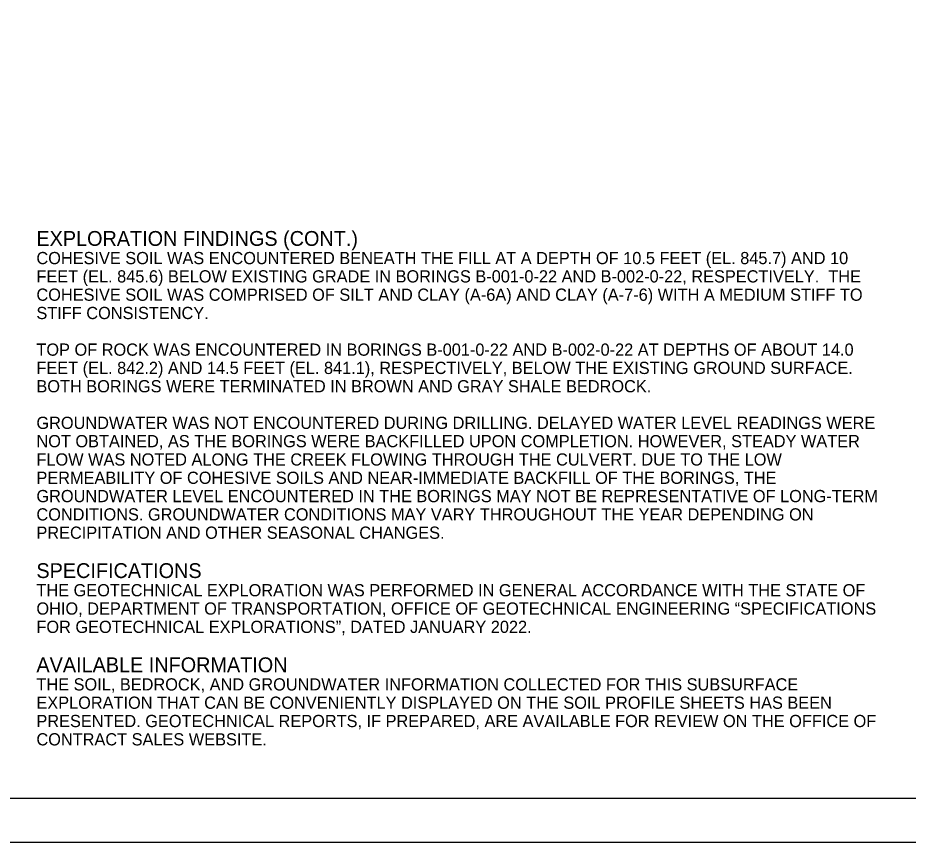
# Model space of a CAD drawing. Extents: x 0 to 34, y 0 to 22.
# Drawn here: x 11.81 to 22.03, y 0 to 9.46 of the extents above; entities that cross this region are included whole.
import ezdxf

# ---------------------------------------------------------------- set-up
doc = ezdxf.new("R2010")
doc.units = 0
for name, color, linetype in [('SH_Border', 7, 'Continuous'), ('SH_Cut_Line', 7, 'Continuous'), ('SH_Text', 7, 'Continuous')]:
    doc.layers.add(name, color=color, linetype=linetype)

msp = doc.modelspace()

# ---------------------------------------------------------------- linework, layer by layer
at = {"layer": 'SH_Border'}
msp.add_lwpolyline([(1.5, 21.5), (33.5, 21.5), (33.5, 0.5), (1.5, 0.5)], close=True, dxfattribs=at)
at = {"layer": 'SH_Cut_Line'}
msp.add_lwpolyline([(0, 0), (34, 0), (34, 22), (0, 22)], close=True, dxfattribs=at)

# ---------------------------------------------------------------- texts
at = {"layer": 'SH_Text'}
for s, height, p in [('EXPLORATION FINDINGS (CONT.)', 0.17, (12.028, 6.84)), ('COHESIVE SOIL WAS ENCOUNTERED BENEATH THE FILL AT A DEPTH OF 10.5 FEET (EL. 845.7) AND 10 ', 0.14, (12.028, 6.63)), ('FEET (EL. 845.6) BELOW EXISTING GRADE IN BORINGS B-001-0-22 AND B-002-0-22, RESPECTIVELY.  THE ', 0.14, (12.028, 6.42)), ('COHESIVE SOIL WAS COMPRISED OF SILT AND CLAY (A-6A) AND CLAY (A-7-6) WITH A MEDIUM STIFF TO ', 0.14, (12.028, 6.21)), ('STIFF CONSISTENCY.', 0.14, (12.028, 6)), ('TOP OF ROCK WAS ENCOUNTERED IN BORINGS B-001-0-22 AND B-002-0-22 AT DEPTHS OF ABOUT 14.0 ', 0.14, (12.028, 5.58)), ('FEET (EL. 842.2) AND 14.5 FEET (EL. 841.1), RESPECTIVELY, BELOW THE EXISTING GROUND SURFACE. ', 0.14, (12.028, 5.37)), ('BOTH BORINGS WERE TERMINATED IN BROWN AND GRAY SHALE BEDROCK. ', 0.14, (12.028, 5.16)), ('GROUNDWATER WAS NOT ENCOUNTERED DURING DRILLING. DELAYED WATER LEVEL READINGS WERE ', 0.14, (12.028, 4.74)), ('NOT OBTAINED, AS THE BORINGS WERE BACKFILLED UPON COMPLETION. HOWEVER, STEADY WATER ', 0.14, (12.028, 4.53)), ('FLOW WAS NOTED ALONG THE CREEK FLOWING THROUGH THE CULVERT. DUE TO THE LOW ', 0.14, (12.028, 4.32)), ('PERMEABILITY OF COHESIVE SOILS AND NEAR-IMMEDIATE BACKFILL OF THE BORINGS, THE ', 0.14, (12.028, 4.11)), ('GROUNDWATER LEVEL ENCOUNTERED IN THE BORINGS MAY NOT BE REPRESENTATIVE OF LONG-TERM ', 0.14, (12.028, 3.9)), ('CONDITIONS. GROUNDWATER CONDITIONS MAY VARY THROUGHOUT THE YEAR DEPENDING ON ', 0.14, (12.028, 3.69)), ('PRECIPITATION AND OTHER SEASONAL CHANGES.', 0.14, (12.028, 3.48)), ('SPECIFICATIONS', 0.17, (12.028, 3.03)), ('THE GEOTECHNICAL EXPLORATION WAS PERFORMED IN GENERAL ACCORDANCE WITH THE STATE OF ', 0.14, (12.028, 2.82)), ('OHIO, DEPARTMENT OF TRANSPORTATION, OFFICE OF GEOTECHNICAL ENGINEERING “SPECIFICATIONS ', 0.14, (12.028, 2.61)), ('FOR GEOTECHNICAL EXPLORATIONS”, DATED JANUARY 2022.', 0.14, (12.028, 2.4)), ('AVAILABLE INFORMATION', 0.17, (12.028, 1.95)), ('THE SOIL, BEDROCK, AND GROUNDWATER INFORMATION COLLECTED FOR THIS SUBSURFACE ', 0.14, (12.028, 1.74)), ('EXPLORATION THAT CAN BE CONVENIENTLY DISPLAYED ON THE SOIL PROFILE SHEETS HAS BEEN ', 0.14, (12.028, 1.53)), ('PRESENTED. GEOTECHNICAL REPORTS, IF PREPARED, ARE AVAILABLE FOR REVIEW ON THE OFFICE OF ', 0.14, (12.028, 1.32)), ('CONTRACT SALES WEBSITE. ', 0.14, (12.028, 1.11))]:
    msp.add_text(s, height=height, dxfattribs=at).set_placement(p)

doc.saveas('drawing.dxf')
